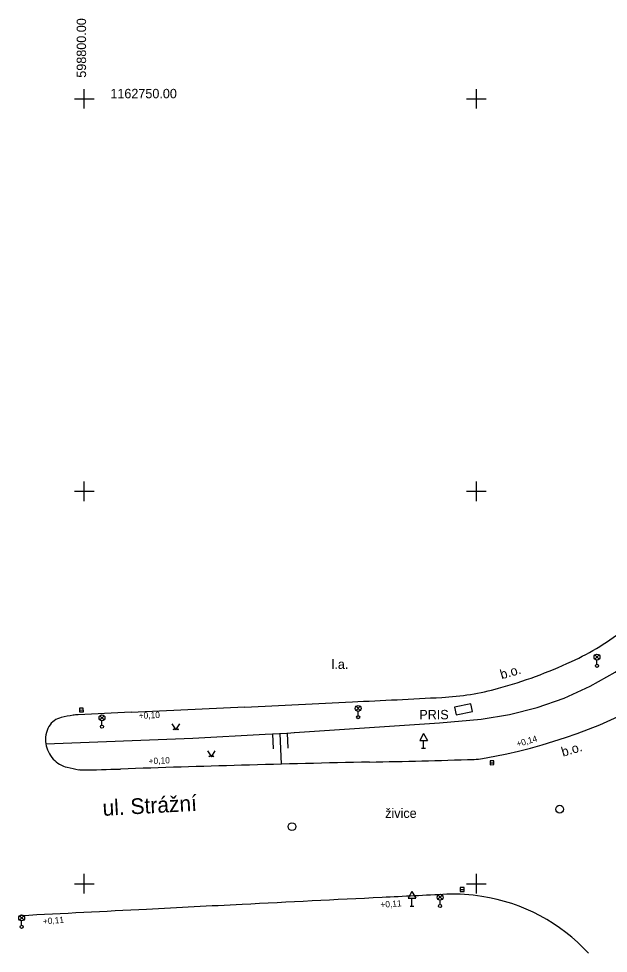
# Model space of a CAD drawing. Extents: x -599151 to -598424, y -1163476 to -1161924.
# Drawn here: x -598804.2 to -598766.6, y -1162804.4 to -1162744.9 of the extents above; entities that cross this region are included whole.
import ezdxf

# ---------------------------------------------------------------- set-up
doc = ezdxf.new("R2010")
doc.units = 0
for name, color, linetype in [('Vrstva 14', 7, 'Continuous'), ('Vrstva 19', 7, 'Continuous'), ('Vrstva 25', 7, 'Continuous'), ('Vrstva 29', 7, 'Continuous'), ('Vrstva 41', 7, 'Continuous'), ('Vrstva 42', 7, 'Continuous'), ('Vrstva 49', 7, 'Continuous'), ('Vrstva 50', 7, 'Continuous'), ('Vrstva 52', 7, 'Continuous'), ('Vrstva 62', 7, 'Continuous'), ('Vrstva 7', 7, 'Continuous')]:
    doc.layers.add(name, color=color, linetype=linetype)

msp = doc.modelspace()

# ---------------------------------------------------------------- linework, layer by layer
at = {"layer": 'Vrstva 14'}
for points in [[(-598794.409, -1162789.812), (-598794.159, -1162790.187), (-598793.909, -1162789.812)], [(-598792.148, -1162791.53), (-598791.898, -1162791.905), (-598791.648, -1162791.53)]]:
    msp.add_lwpolyline(points, dxfattribs=at)
for centre in [(-598794.284, -1162790.162), (-598794.034, -1162790.162), (-598792.023, -1162791.88), (-598791.773, -1162791.88)]:
    msp.add_circle(centre, 0.025, dxfattribs=at)
at = {"layer": 'Vrstva 19'}
for p, q in [((-598778.37, -1162790.438), (-598778.62, -1162790.871)), ((-598778.62, -1162790.871), (-598778.12, -1162790.871)), ((-598778.37, -1162790.438), (-598778.12, -1162790.871)), ((-598778.37, -1162791.371), (-598778.37, -1162790.871)), ((-598778.495, -1162791.371), (-598778.245, -1162791.371)), ((-598779.11, -1162800.488), (-598779.36, -1162800.921)), ((-598779.11, -1162800.488), (-598778.86, -1162800.921)), ((-598779.36, -1162800.921), (-598778.86, -1162800.921)), ((-598779.11, -1162801.421), (-598779.11, -1162800.921)), ((-598779.235, -1162801.421), (-598778.985, -1162801.421))]:
    msp.add_line(p, q, dxfattribs=at)
at = {"layer": 'Vrstva 25'}
for p, q in [((-598800.305, -1162788.933), (-598800.055, -1162788.929)), ((-598774.135, -1162792.292), (-598773.885, -1162792.288)), ((-598776.035, -1162800.363), (-598775.785, -1162800.359))]:
    msp.add_line(p, q, dxfattribs=at)
for points in [[(-598800.303, -1162789.058), (-598800.053, -1162789.054), (-598800.057, -1162788.804), (-598800.307, -1162788.808)], [(-598774.133, -1162792.417), (-598773.883, -1162792.413), (-598773.887, -1162792.163), (-598774.137, -1162792.167)], [(-598776.033, -1162800.488), (-598775.783, -1162800.484), (-598775.787, -1162800.234), (-598776.037, -1162800.238)]]:
    msp.add_lwpolyline(points, close=True, dxfattribs=at)
for centre in [(-598769.7, -1162795.25), (-598786.76, -1162796.361)]:
    msp.add_circle(centre, 0.25, dxfattribs=at)
at = {"layer": 'Vrstva 29'}
for p, q in [((-598767.452, -1162785.69), (-598767.188, -1162785.426)), ((-598767.184, -1162785.689), (-598767.448, -1162785.424)), ((-598767.32, -1162786.021), (-598767.32, -1162785.746)), ((-598782.672, -1162788.96), (-598782.408, -1162788.696)), ((-598782.404, -1162788.959), (-598782.668, -1162788.694)), ((-598782.54, -1162789.291), (-598782.54, -1162789.016)), ((-598799.002, -1162789.559), (-598798.738, -1162789.295)), ((-598798.734, -1162789.558), (-598798.998, -1162789.293)), ((-598798.87, -1162789.89), (-598798.87, -1162789.615)), ((-598777.452, -1162800.99), (-598777.188, -1162800.726)), ((-598777.184, -1162800.989), (-598777.448, -1162800.724)), ((-598777.32, -1162801.321), (-598777.32, -1162801.046)), ((-598804.122, -1162802.309), (-598803.858, -1162802.045)), ((-598803.854, -1162802.308), (-598804.118, -1162802.043)), ((-598803.99, -1162802.64), (-598803.99, -1162802.365))]:
    msp.add_line(p, q, dxfattribs=at)
msp.add_lwpolyline([(-598776.29, -1162789.239), (-598775.26, -1162789.029), (-598775.36, -1162788.541), (-598776.39, -1162788.751)], close=True, dxfattribs=at)
for centre, radius in [((-598767.32, -1162785.559), 0.188), ((-598767.32, -1162786.121), 0.1), ((-598782.54, -1162788.829), 0.188), ((-598798.87, -1162789.427), 0.188), ((-598782.54, -1162789.391), 0.1), ((-598798.87, -1162789.99), 0.1), ((-598777.32, -1162800.859), 0.188), ((-598777.32, -1162801.421), 0.1), ((-598803.99, -1162802.177), 0.188), ((-598803.99, -1162802.74), 0.1)]:
    msp.add_circle(centre, radius, dxfattribs=at)
at = {"layer": 'Vrstva 41'}
for points in [[(-598786.592, -1162790.369), (-598777.359, -1162789.744), (-598774.7, -1162789.52), (-598772.899, -1162789.225), (-598771.131, -1162788.774), (-598769.409, -1162788.17), (-598767.746, -1162787.417), (-598766.156, -1162786.522), (-598764.65, -1162785.491), (-598763.463, -1162784.529), (-598760.846, -1162782.344), (-598759.871, -1162781.474)], [(-598787.526, -1162790.424), (-598787.058, -1162790.397)], [(-598787.526, -1162790.411), (-598787.526, -1162790.424)], [(-598787.059, -1162790.382), (-598787.058, -1162790.397)], [(-598787.058, -1162790.397), (-598786.592, -1162790.369)], [(-598787.058, -1162790.397), (-598787.024, -1162791.37)], [(-598786.593, -1162790.352), (-598786.592, -1162790.369)], [(-598802.45, -1162791.08), (-598793.078, -1162790.715), (-598788.459, -1162790.477)], [(-598788.459, -1162790.477), (-598787.993, -1162790.451)], [(-598787.993, -1162790.451), (-598787.526, -1162790.424)], [(-598787.993, -1162790.44), (-598787.993, -1162790.451)], [(-598787.993, -1162790.451), (-598787.958, -1162791.415)], [(-598787.526, -1162790.424), (-598787.456, -1162792.383)]]:
    msp.add_lwpolyline(points, dxfattribs=at)
at = {"layer": 'Vrstva 62'}
for p, q in [((-598800, -1162750.625), (-598800, -1162749.375)), ((-598775, -1162750.625), (-598775, -1162749.375)), ((-598800.625, -1162750), (-598799.375, -1162750)), ((-598775.625, -1162750), (-598774.375, -1162750)), ((-598800, -1162775.625), (-598800, -1162774.375)), ((-598775, -1162775.625), (-598775, -1162774.375)), ((-598800.625, -1162775), (-598799.375, -1162775)), ((-598775.625, -1162775), (-598774.375, -1162775)), ((-598800, -1162800.625), (-598800, -1162799.375)), ((-598775, -1162800.625), (-598775, -1162799.375)), ((-598800.625, -1162800), (-598799.375, -1162800)), ((-598775.625, -1162800), (-598774.375, -1162800))]:
    msp.add_line(p, q, dxfattribs=at)
at = {"layer": 'Vrstva 7'}
for centre, radius, start, end in [((-598780.571, -1162757.313), 35.215, 279.74509, 320.18839), ((-598776.284, -1162769.931), 17.528, 294.73774, 308.1696), ((-598781.683, -1162758.213), 30.429, 285.43105, 294.73774), ((-598778.06, -1162771.341), 16.811, 272.89876, 285.43105), ((-598980.25, -1158728.411), 4064.796, 272.686067, 272.782705), ((-598919.739, -1159973.349), 2818.388, 272.782706, 272.898761), ((-598768.614, -1163427.787), 639.346, 92.546084, 92.847933), ((-598929.08, -1159819.119), 2972.887, 272.546086, 272.686067), ((-598801.198, -1162790.6), 1.218, 102.39481, 149.33993), ((-598798.276, -1162803.897), 14.832, 99.46232, 102.39481), ((-598800.235, -1162792.145), 2.918, 92.84793, 99.46232), ((-598800.85, -1162790.807), 1.623, 149.33993, 189.70887), ((-598800.551, -1162790.756), 1.927, 189.70887, 222.40649), ((-598800.674, -1162790.868), 1.76, 222.40649, 256.66528), ((-598798.373, -1162008.874), 783.55, 271.211225, 271.698397), ((-598776.479, -1162777.77), 14.372, 275.30696, 277.47249), ((-598798.072, -1162779.891), 13.041, 256.66528, 259.95798), ((-598800.137, -1162791.554), 1.196, 259.95799, 270.84469), ((-598801.961, -1162667.847), 124.917, 270.84469, 271.96009), ((-598754.599, -1164051.768), 1259.814, 91.608869, 91.960093), ((-598756.949, -1163968.081), 1176.094, 91.211225, 91.608869), ((-597695.122, -1184602.289), 21828.442, 92.8514563, 92.8749078), ((-598548.801, -1167463.042), 4667.948, 92.800743, 92.851456), ((-598776.482, -1162812.172), 11.508, 80.83959, 92.03004), ((-598776.347, -1162812.171), 11.487, 42.36874, 81.50381), ((-598184.746, -1174764.088), 11978.067, 92.925274, 92.9635984), ((-598442.101, -1169727.8), 6935.208, 92.8749078, 92.9252739)]:
    msp.add_arc(centre, radius, start, end, dxfattribs=at)

# ---------------------------------------------------------------- texts
at = {"layer": 'Vrstva 42'}
msp.add_text('ul. Strážní', height=1, rotation=3.11863, dxfattribs=at).set_placement((-598798.806, -1162795.677))
at = {"layer": 'Vrstva 49'}
for s, p in [('l.a.', (-598784.235, -1162786.314)), ('PRIS', (-598778.643, -1162789.525)), ('živice', (-598780.819, -1162795.805))]:
    msp.add_text(s, height=0.6, dxfattribs=at).set_placement(p)
for p in [(-598773.392, -1162786.98), (-598769.489, -1162791.909)]:
    msp.add_text('b.o.', height=0.6, rotation=16.48767, dxfattribs=at).set_placement(p)
at = {"layer": 'Vrstva 50'}
for s, rotation, p in [('+0,10', 2.62012, (-598796.52, -1162789.498)), ('+0,14', 16.09055, (-598772.39, -1162791.296)), ('+0,10', 2.62012, (-598795.887, -1162792.389)), ('+0,11', 4.16298, (-598781.107, -1162801.535)), ('+0,11', 4.16298, (-598802.624, -1162802.589))]:
    msp.add_text(s, height=0.4, rotation=rotation, dxfattribs=at).set_placement(p)
at = {"layer": 'Vrstva 52'}
msp.add_text('598800.00', height=0.6, rotation=90, dxfattribs=at).set_placement((-598799.882, -1162748.656))
msp.add_text('1162750.00', height=0.6, dxfattribs=at).set_placement((-598798.335, -1162749.964))

doc.saveas('drawing.dxf')
